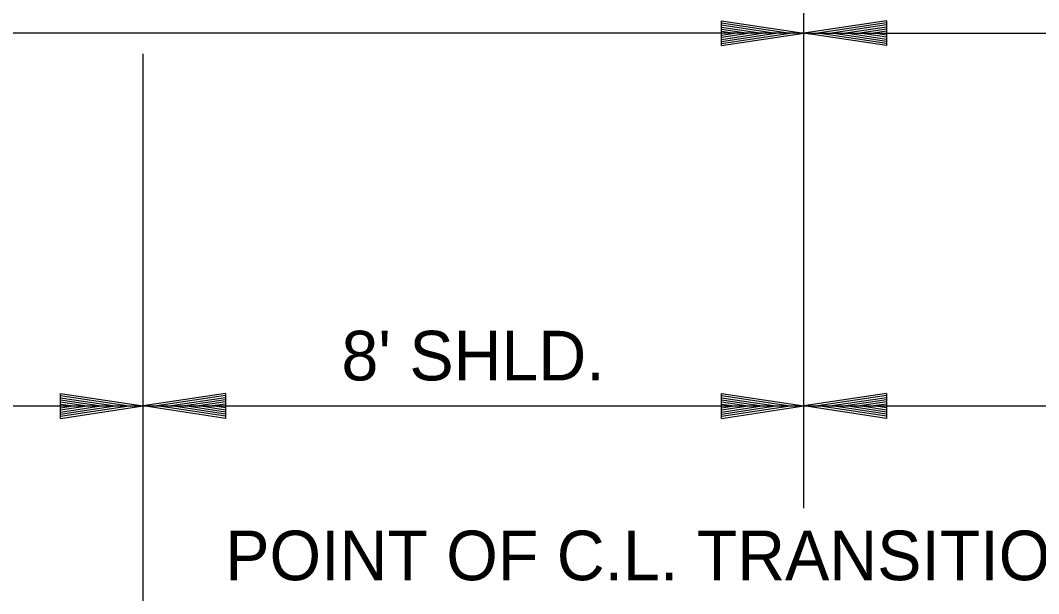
# Model space of a CAD drawing. Extents: x 1955768 to 1955917, y 566446 to 566546.
# Drawn here: x 1955818.19 to 1955830.51, y 566522.92 to 566529.86 of the extents above; entities that cross this region are included whole.
import ezdxf

# ---------------------------------------------------------------- set-up
doc = ezdxf.new("R2010")
doc.units = 0
doc.layers.add('R_Border', color=7, linetype='Continuous')
doc.layers.add('R_Grid', color=7, linetype='Continuous')

msp = doc.modelspace()

# ---------------------------------------------------------------- linework, layer by layer
at = {"layer": 'R_Grid'}
for p, q in [((1955827.673, 566523.959), (1955827.673, 566535.038)), ((1955826.673, 566529.858), (1955827.673, 566529.708)), ((1955826.673, 566529.558), (1955826.673, 566529.858)), ((1955828.673, 566529.858), (1955827.673, 566529.708)), ((1955828.673, 566529.858), (1955828.673, 566529.558)), ((1955826.673, 566529.833), (1955827.506, 566529.708)), ((1955826.673, 566529.807), (1955827.334, 566529.708)), ((1955826.673, 566529.782), (1955827.168, 566529.708)), ((1955826.673, 566529.757), (1955826.998, 566529.708)), ((1955828.673, 566529.833), (1955827.84, 566529.708)), ((1955828.673, 566529.807), (1955828.012, 566529.708)), ((1955828.673, 566529.782), (1955828.179, 566529.708)), ((1955828.673, 566529.756), (1955828.348, 566529.708)), ((1955827.673, 566529.708), (1955797.673, 566529.708)), ((1955826.673, 566529.731), (1955826.831, 566529.708)), ((1955826.673, 566529.558), (1955827.673, 566529.708)), ((1955826.673, 566529.659), (1955826.998, 566529.708)), ((1955826.673, 566529.608), (1955827.334, 566529.708)), ((1955826.673, 566529.583), (1955827.506, 566529.708)), ((1955826.673, 566529.633), (1955827.168, 566529.708)), ((1955826.673, 566529.684), (1955826.831, 566529.708)), ((1955827.673, 566529.708), (1955851.672, 566529.708)), ((1955828.673, 566529.558), (1955827.673, 566529.708)), ((1955828.673, 566529.583), (1955827.84, 566529.708)), ((1955828.673, 566529.608), (1955828.012, 566529.708)), ((1955828.673, 566529.633), (1955828.179, 566529.708)), ((1955828.673, 566529.659), (1955828.348, 566529.708)), ((1955828.673, 566529.731), (1955828.515, 566529.708)), ((1955828.673, 566529.684), (1955828.515, 566529.708)), ((1955819.673, 566526.223), (1955819.673, 566529.458)), ((1955819.673, 566519.79), (1955819.673, 566526.223)), ((1955818.673, 566525.345), (1955819.673, 566525.195)), ((1955818.673, 566525.045), (1955818.673, 566525.345)), ((1955818.673, 566525.32), (1955819.506, 566525.195)), ((1955820.673, 566525.345), (1955819.673, 566525.195)), ((1955820.673, 566525.32), (1955819.84, 566525.195)), ((1955820.673, 566525.345), (1955820.673, 566525.045)), ((1955826.673, 566525.345), (1955827.673, 566525.195)), ((1955826.673, 566525.045), (1955826.673, 566525.345)), ((1955826.673, 566525.32), (1955827.506, 566525.195)), ((1955828.673, 566525.345), (1955827.673, 566525.195)), ((1955828.673, 566525.32), (1955827.84, 566525.195)), ((1955828.673, 566525.345), (1955828.673, 566525.045)), ((1955813.423, 566525.195), (1955819.673, 566525.195)), ((1955818.673, 566525.295), (1955819.334, 566525.195)), ((1955818.673, 566525.27), (1955819.168, 566525.195)), ((1955818.673, 566525.244), (1955818.998, 566525.195)), ((1955818.673, 566525.219), (1955818.831, 566525.195)), ((1955818.673, 566525.045), (1955819.673, 566525.195)), ((1955818.673, 566525.147), (1955818.998, 566525.195)), ((1955818.673, 566525.096), (1955819.334, 566525.195)), ((1955818.673, 566525.07), (1955819.506, 566525.195)), ((1955818.673, 566525.121), (1955819.168, 566525.195)), ((1955818.673, 566525.172), (1955818.831, 566525.195)), ((1955820.673, 566525.045), (1955819.673, 566525.195)), ((1955819.673, 566525.195), (1955827.673, 566525.195)), ((1955820.673, 566525.07), (1955819.84, 566525.195)), ((1955820.673, 566525.295), (1955820.012, 566525.195)), ((1955820.673, 566525.096), (1955820.012, 566525.195)), ((1955820.673, 566525.27), (1955820.179, 566525.195)), ((1955820.673, 566525.121), (1955820.179, 566525.195)), ((1955820.673, 566525.244), (1955820.348, 566525.195)), ((1955820.673, 566525.146), (1955820.348, 566525.195)), ((1955820.673, 566525.219), (1955820.515, 566525.195)), ((1955820.673, 566525.172), (1955820.515, 566525.195)), ((1955826.673, 566525.295), (1955827.334, 566525.195)), ((1955826.673, 566525.27), (1955827.168, 566525.195)), ((1955826.673, 566525.244), (1955826.998, 566525.195)), ((1955826.673, 566525.219), (1955826.831, 566525.195)), ((1955826.673, 566525.045), (1955827.673, 566525.195)), ((1955826.673, 566525.147), (1955826.998, 566525.195)), ((1955826.673, 566525.096), (1955827.334, 566525.195)), ((1955826.673, 566525.07), (1955827.506, 566525.195)), ((1955826.673, 566525.121), (1955827.168, 566525.195)), ((1955826.673, 566525.172), (1955826.831, 566525.195)), ((1955828.673, 566525.045), (1955827.673, 566525.195)), ((1955827.673, 566525.195), (1955839.673, 566525.195)), ((1955828.673, 566525.07), (1955827.84, 566525.195)), ((1955828.673, 566525.295), (1955828.012, 566525.195)), ((1955828.673, 566525.096), (1955828.012, 566525.195)), ((1955828.673, 566525.27), (1955828.179, 566525.195)), ((1955828.673, 566525.121), (1955828.179, 566525.195)), ((1955828.673, 566525.244), (1955828.348, 566525.195)), ((1955828.673, 566525.146), (1955828.348, 566525.195)), ((1955828.673, 566525.219), (1955828.515, 566525.195)), ((1955828.673, 566525.172), (1955828.515, 566525.195))]:
    msp.add_line(p, q, dxfattribs=at)

# ---------------------------------------------------------------- texts
at = {"layer": 'R_Border'}
for s, p in [("8' SHLD.", (1955822.075, 566525.505)), ('POINT OF C.L. TRANSITION ROTATION', (1955820.669, 566523.086))]:
    msp.add_text(s, height=0.6, dxfattribs=at).set_placement(p)

doc.saveas('drawing.dxf')
